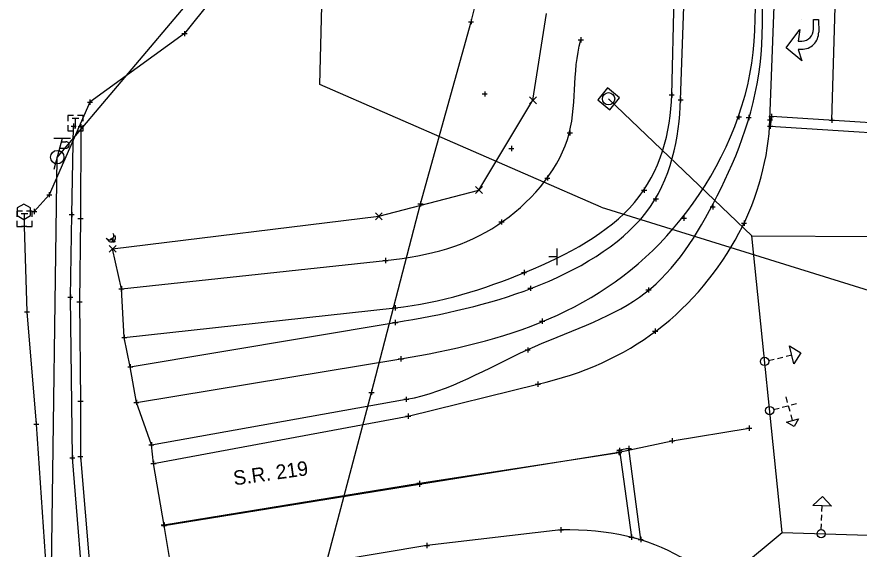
# Model space of a CAD drawing. Extents: x 1391912 to 1392597, y 304167 to 305226.
# Drawn here: x 1392159.5 to 1392322.5, y 304441.7 to 304544.7 of the extents above; entities that cross this region are included whole.
import ezdxf

# ---------------------------------------------------------------- set-up
doc = ezdxf.new("R2010")
doc.units = 0
for name, color, linetype in [('_CIVIL_CONSTRUCTION', 7, 'Continuous'), ('DV_X_Property_Line', 7, 'Continuous'), ('DV_X_Section_VMS_Line', 7, 'Continuous'), ('PM_X_Channelizing_Line', 7, 'Continuous'), ('PM_X_CL_Pass_Proh_Lt', 7, 'Continuous'), ('PM_X_Edge_Line', 7, 'Continuous'), ('PM_X_Stop_Line', 7, 'Continuous'), ('PV_X_COP', 7, 'Continuous'), ('PV_X_EOP', 7, 'Continuous'), ('PV_X_Shoulder_Aggregate', 7, 'Continuous'), ('RW_X_CL_100_Bearings', 7, 'Continuous'), ('RW_X_CL_100_Distances', 7, 'Continuous'), ('RW_X_Esmt_SH', 7, 'Continuous'), ('SC_Scratch6', 7, 'Continuous'), ('SG_X_Heads', 7, 'Continuous'), ('SG_X_Messenger_Wire', 7, 'Continuous'), ('SV_X_Break_Lines', 7, 'Continuous'), ('SV_X_Terrain_Boundary', 7, 'Continuous'), ('SV_X_Text', 7, 'Continuous'), ('SV_X_Toe_of_Slope', 7, 'Continuous'), ('SV_X_Top_of_Bank', 7, 'Continuous'), ('UT_X_FO', 7, 'Continuous'), ('UT_X_Gas', 7, 'Continuous'), ('UT_X_Overhead_Combined', 7, 'Continuous'), ('UT_X_Sanitary_Pressure_Line', 7, 'Continuous'), ('UT_X_Telecom_Cells', 7, 'Continuous')]:
    doc.layers.add(name, color=color, linetype=linetype)

msp = doc.modelspace()

# ---------------------------------------------------------------- linework, layer by layer
at = {"layer": '_CIVIL_CONSTRUCTION'}
for p, q in [((1392264, 304499.86), (1392264, 304496.66)), ((1392264, 304498.26), (1392262.4, 304498.26))]:
    msp.add_line(p, q, dxfattribs=at)
at = {"layer": 'DV_X_Property_Line'}
for p, q in [((1392311.31, 304544.17), (1392311.31, 304544.17)), ((1392313.64, 304544.19), (1392314.64, 304544.2)), ((1392313.66, 304542.33), (1392313.64, 304544.19)), ((1392314.64, 304544.2), (1392314.66, 304541.73)), ((1392308.36, 304538.71), (1392310.99, 304542.25)), ((1392310.99, 304542.25), (1392310.68, 304540.01)), ((1392310.68, 304540.01), (1392311.38, 304540.01)), ((1392311.38, 304536.17), (1392308.36, 304538.71)), ((1392311.36, 304538.41), (1392310.69, 304538.41)), ((1392310.69, 304538.41), (1392311.38, 304536.17)), ((1392311.38, 304536.17), (1392311.38, 304536.17))]:
    msp.add_line(p, q, dxfattribs=at)
for centre, radius, start in [((1392311.38, 304541.7), 3.28, 269.6131), ((1392311.36, 304542.31), 2.3, 270.5216)]:
    msp.add_arc(centre, radius, start, 0.5216, dxfattribs=at)
at = {"layer": 'DV_X_Section_VMS_Line'}
for p, q in [((1392258.7, 304527.88), (1392260.03, 304529.22)), ((1392258.7, 304529.22), (1392260.03, 304527.88)), ((1392248.24, 304510.5), (1392249.57, 304511.84)), ((1392248.24, 304511.84), (1392249.57, 304510.5)), ((1392228.85, 304505.43), (1392230.18, 304506.76)), ((1392228.85, 304506.76), (1392230.18, 304505.43)), ((1392177.33, 304499.13), (1392178.66, 304500.47)), ((1392177.33, 304500.47), (1392178.66, 304499.13))]:
    msp.add_line(p, q, dxfattribs=at)
at = {"layer": 'PM_X_Channelizing_Line'}
msp.add_lwpolyline([(1392317.22, 304524.68), (1392318.62, 304572.95), (1392319.87, 304618.22)], dxfattribs=at)
at = {"layer": 'PM_X_CL_Pass_Proh_Lt'}
msp.add_lwpolyline([(1392187.91, 304446.39), (1392237.38, 304454.42), (1392276.03, 304460.35)], dxfattribs=at)
at = {"layer": 'PM_X_Edge_Line'}
for p, q in [((1392305.23, 304524.78), (1392307, 304573.68)), ((1392235.19, 304467.42), (1392260.31, 304473.6)), ((1392185.92, 304458.25), (1392235.19, 304467.42)), ((1392264.78, 304445.4), (1392238.83, 304442.38)), ((1392238.83, 304442.38), (1392189.99, 304434.24))]:
    msp.add_line(p, q, dxfattribs=at)
for points in [[(1392260.31, 304473.6), (1392268.98, 304475.58), (1392284.55, 304482.46), (1392300.93, 304502.32), (1392304.96, 304517.51), (1392305.23, 304524.78)], [(1392310.98, 304404.01), (1392310.09, 304411.72), (1392305.75, 304424.92), (1392288.84, 304442.14), (1392274.13, 304445.52), (1392264.78, 304445.4)]]:
    msp.add_open_spline(points, degree=3, dxfattribs=at)
at = {"layer": 'PM_X_Stop_Line'}
for points in [[(1392305.5, 304525.42), (1392305.28, 304523.52), (1392341.75, 304521.19), (1392341.84, 304523.06)], [(1392278.4, 304444), (1392280.21, 304443.54), (1392277.9, 304461.18), (1392276.09, 304460.8)]]:
    msp.add_lwpolyline(points, close=True, dxfattribs=at)
at = {"layer": 'PV_X_COP'}
msp.add_lwpolyline([(1392187.94, 304446.23), (1392237.37, 304454.26), (1392275.96, 304460.46), (1392286.28, 304462.65), (1392301.21, 304465.09)], dxfattribs=at)
at = {"layer": 'PV_X_EOP'}
msp.add_line((1392185.5, 304461.86), (1392234.84, 304470.67), dxfattribs=at)
msp.add_open_spline([(1392234.84, 304470.67), (1392243.18, 304472.16), (1392258, 304481.34), (1392281.79, 304488.52), (1392294.5, 304507.17), (1392305.92, 304534.51), (1392303.1, 304556.6), (1392303.68, 304573.91)], degree=3, dxfattribs=at)
at = {"layer": 'PV_X_Shoulder_Aggregate'}
msp.add_line((1392182.59, 304470.07), (1392233.78, 304478.51), dxfattribs=at)
msp.add_open_spline([(1392233.78, 304478.51), (1392243.5, 304480.11), (1392263.28, 304484.58), (1392287.78, 304501.2), (1392305.02, 304533.31), (1392301.84, 304556.01), (1392301.83, 304573.96)], degree=3, dxfattribs=at)
at = {"layer": 'RW_X_CL_100_Bearings'}
msp.add_lwpolyline([(1392159.52, 304506.22), (1392160.81, 304505.47), (1392162.11, 304506.22), (1392162.11, 304507.72), (1392160.81, 304508.47), (1392159.52, 304507.72), (1392159.52, 304506.22)], dxfattribs=at)
at = {"layer": 'RW_X_CL_100_Distances'}
for p, q in [((1392169.84, 304521.14), (1392166.64, 304521.14)), ((1392168.24, 304521.14), (1392166.64, 304515.14)), ((1392168.08, 304520.54), (1392168.93, 304520.54)), ((1392167.74, 304519.26), (1392168.93, 304519.26))]:
    msp.add_line(p, q, dxfattribs=at)
for centre, radius in [((1392167.28, 304517.54), 1.3), ((1392177.87, 304501.68), 0.2), ((1392178.2, 304501.26), 0.2)]:
    msp.add_circle(centre, radius, dxfattribs=at)
for centre, radius, start, end in [((1392168.95, 304519.9), 0.638, 268.8767, 91.1233), ((1392177.42, 304502.34), 0.8, 214.6385, 34.6385), ((1392177.75, 304501.92), 0.8, 214.451, 34.451)]:
    msp.add_arc(centre, radius, start, end, dxfattribs=at)
at = {"layer": 'RW_X_Esmt_SH'}
for p, q in [((1392246.86, 304543.76), (1392247.86, 304543.76)), ((1392247.36, 304544.26), (1392247.36, 304543.26)), ((1392247.36, 304543.76), (1392247.36, 304543.76)), ((1392191.89, 304541.96), (1392191.89, 304540.96)), ((1392191.39, 304541.46), (1392192.39, 304541.46)), ((1392191.89, 304541.46), (1392191.89, 304541.46)), ((1392268.13, 304540.24), (1392269.13, 304540.24)), ((1392268.63, 304540.74), (1392268.63, 304539.74)), ((1392268.63, 304540.24), (1392268.63, 304540.24)), ((1392250.02, 304530.28), (1392250.02, 304529.28)), ((1392173.6, 304528.69), (1392173.6, 304527.69)), ((1392249.52, 304529.78), (1392250.52, 304529.78)), ((1392250.02, 304529.78), (1392250.02, 304529.78)), ((1392285.71, 304529.59), (1392286.71, 304529.59)), ((1392286.21, 304530.09), (1392286.21, 304529.09)), ((1392286.21, 304529.59), (1392286.21, 304529.59)), ((1392287.44, 304528.66), (1392288.44, 304528.66)), ((1392287.94, 304529.16), (1392287.94, 304528.16)), ((1392287.94, 304528.66), (1392287.94, 304528.66)), ((1392173.1, 304528.19), (1392174.1, 304528.19)), ((1392173.6, 304528.19), (1392173.6, 304528.19)), ((1392298.72, 304525.35), (1392299.72, 304525.35)), ((1392299.22, 304525.85), (1392299.22, 304524.85)), ((1392299.22, 304525.35), (1392299.22, 304525.35)), ((1392301.11, 304525.71), (1392301.11, 304524.71)), ((1392305, 304525.42), (1392306, 304525.42)), ((1392305.23, 304525.28), (1392305.23, 304524.28)), ((1392305.5, 304525.92), (1392305.5, 304524.92)), ((1392305.5, 304525.42), (1392305.5, 304525.42)), ((1392170.44, 304524.04), (1392170.44, 304523.04)), ((1392171.84, 304523.96), (1392171.84, 304522.96)), ((1392300.61, 304525.21), (1392301.61, 304525.21)), ((1392301.11, 304525.21), (1392301.11, 304525.21)), ((1392304.73, 304524.78), (1392305.73, 304524.78)), ((1392305.23, 304524.78), (1392305.23, 304524.78)), ((1392305.28, 304524.02), (1392305.28, 304523.02)), ((1392316.72, 304524.68), (1392317.72, 304524.68)), ((1392317.22, 304525.18), (1392317.22, 304524.18)), ((1392317.22, 304524.68), (1392317.22, 304524.68)), ((1392169.94, 304523.54), (1392170.94, 304523.54)), ((1392170.44, 304523.54), (1392170.44, 304523.54)), ((1392171.34, 304523.46), (1392172.34, 304523.46)), ((1392171.84, 304523.46), (1392171.84, 304523.46)), ((1392265.99, 304522.22), (1392266.99, 304522.22)), ((1392266.49, 304522.72), (1392266.49, 304521.72)), ((1392266.49, 304522.22), (1392266.49, 304522.22)), ((1392304.78, 304523.52), (1392305.78, 304523.52)), ((1392305.28, 304523.52), (1392305.28, 304523.52)), ((1392254.68, 304519.21), (1392255.68, 304519.21)), ((1392255.18, 304519.71), (1392255.18, 304518.71)), ((1392255.18, 304519.21), (1392255.18, 304519.21)), ((1392262.14, 304514), (1392262.14, 304513)), ((1392261.64, 304513.5), (1392262.64, 304513.5)), ((1392262.14, 304513.5), (1392262.14, 304513.5)), ((1392165.73, 304510.78), (1392165.73, 304509.78)), ((1392280.39, 304511.14), (1392281.39, 304511.14)), ((1392280.89, 304511.64), (1392280.89, 304510.64)), ((1392280.89, 304511.14), (1392280.89, 304511.14)), ((1392165.23, 304510.28), (1392166.23, 304510.28)), ((1392165.73, 304510.28), (1392165.73, 304510.28)), ((1392237.57, 304508.98), (1392237.57, 304507.98)), ((1392282.62, 304509.45), (1392283.62, 304509.45)), ((1392283.12, 304509.95), (1392283.12, 304508.95)), ((1392283.12, 304509.45), (1392283.12, 304509.45)), ((1392162.82, 304507.53), (1392162.82, 304506.53)), ((1392237.07, 304508.48), (1392238.07, 304508.48)), ((1392237.57, 304508.48), (1392237.57, 304508.48)), ((1392293.64, 304507.92), (1392294.64, 304507.92)), ((1392294.14, 304508.42), (1392294.14, 304507.42)), ((1392294.14, 304507.92), (1392294.14, 304507.92)), ((1392162.32, 304507.03), (1392163.32, 304507.03)), ((1392162.82, 304507.03), (1392162.82, 304507.03)), ((1392169.57, 304506.42), (1392170.57, 304506.42)), ((1392170.07, 304506.92), (1392170.07, 304505.92)), ((1392170.07, 304506.42), (1392170.07, 304506.42)), ((1392171.29, 304505.68), (1392172.29, 304505.68)), ((1392171.79, 304506.18), (1392171.79, 304505.18)), ((1392171.79, 304505.68), (1392171.79, 304505.68)), ((1392288.06, 304505.71), (1392289.06, 304505.71)), ((1392288.56, 304506.21), (1392288.56, 304505.21)), ((1392288.56, 304505.71), (1392288.56, 304505.71)), ((1392160.38, 304504.2), (1392161.38, 304504.2)), ((1392160.88, 304504.7), (1392160.88, 304503.7)), ((1392160.88, 304504.2), (1392160.88, 304504.2)), ((1392252.76, 304505), (1392253.76, 304505)), ((1392253.26, 304505.5), (1392253.26, 304504.5)), ((1392253.26, 304505), (1392253.26, 304505)), ((1392299.71, 304504.77), (1392300.71, 304504.77)), ((1392300.21, 304505.27), (1392300.21, 304504.27)), ((1392300.21, 304504.77), (1392300.21, 304504.77)), ((1392230.31, 304497.55), (1392231.31, 304497.55)), ((1392230.81, 304498.05), (1392230.81, 304497.05)), ((1392230.81, 304497.55), (1392230.81, 304497.55)), ((1392257.13, 304495.22), (1392258.13, 304495.22)), ((1392257.63, 304495.72), (1392257.63, 304494.72)), ((1392257.63, 304495.22), (1392257.63, 304495.22)), ((1392258.86, 304492.66), (1392258.86, 304491.66)), ((1392179.18, 304492.06), (1392180.18, 304492.06)), ((1392179.68, 304492.56), (1392179.68, 304491.56)), ((1392179.68, 304492.06), (1392179.68, 304492.06)), ((1392258.36, 304492.16), (1392259.36, 304492.16)), ((1392258.86, 304492.16), (1392258.86, 304492.16)), ((1392281.22, 304491.84), (1392282.22, 304491.84)), ((1392281.72, 304492.34), (1392281.72, 304491.34)), ((1392281.72, 304491.84), (1392281.72, 304491.84)), ((1392169.31, 304490.44), (1392170.31, 304490.44)), ((1392169.81, 304490.94), (1392169.81, 304489.94)), ((1392169.81, 304490.44), (1392169.81, 304490.44)), ((1392171.09, 304489.53), (1392172.09, 304489.53)), ((1392171.59, 304490.03), (1392171.59, 304489.03)), ((1392171.59, 304489.53), (1392171.59, 304489.53)), ((1392161.41, 304488.13), (1392161.41, 304487.13)), ((1392232.16, 304488.37), (1392233.16, 304488.37)), ((1392232.66, 304488.87), (1392232.66, 304487.87)), ((1392232.66, 304488.37), (1392232.66, 304488.37)), ((1392160.91, 304487.63), (1392161.91, 304487.63)), ((1392161.41, 304487.63), (1392161.41, 304487.63)), ((1392261.14, 304486.29), (1392261.14, 304485.29)), ((1392232.17, 304485.54), (1392233.17, 304485.54)), ((1392232.67, 304486.04), (1392232.67, 304485.04)), ((1392232.67, 304485.54), (1392232.67, 304485.54)), ((1392260.64, 304485.79), (1392261.64, 304485.79)), ((1392261.14, 304485.79), (1392261.14, 304485.79)), ((1392180.25, 304483.13), (1392180.25, 304482.13)), ((1392282.52, 304483.85), (1392283.52, 304483.85)), ((1392283.02, 304484.35), (1392283.02, 304483.35)), ((1392283.02, 304483.85), (1392283.02, 304483.85)), ((1392179.75, 304482.63), (1392180.75, 304482.63)), ((1392180.25, 304482.63), (1392180.25, 304482.63)), ((1392257.83, 304480.23), (1392258.83, 304480.23)), ((1392258.33, 304480.73), (1392258.33, 304479.73)), ((1392258.33, 304480.23), (1392258.33, 304480.23)), ((1392233.28, 304478.51), (1392234.28, 304478.51)), ((1392233.78, 304479.01), (1392233.78, 304478.01)), ((1392233.78, 304478.51), (1392233.78, 304478.51)), ((1392180.92, 304476.96), (1392181.92, 304476.96)), ((1392181.42, 304477.46), (1392181.42, 304476.46)), ((1392181.42, 304476.96), (1392181.42, 304476.96)), ((1392259.81, 304473.6), (1392260.81, 304473.6)), ((1392260.31, 304474.1), (1392260.31, 304473.1)), ((1392260.31, 304473.6), (1392260.31, 304473.6)), ((1392227.6, 304472.01), (1392228.6, 304472.01)), ((1392228.1, 304472.51), (1392228.1, 304471.51)), ((1392228.1, 304472.01), (1392228.1, 304472.01)), ((1392171.26, 304470.32), (1392172.26, 304470.32)), ((1392171.76, 304470.82), (1392171.76, 304469.82)), ((1392171.76, 304470.32), (1392171.76, 304470.32)), ((1392182.09, 304470.07), (1392183.09, 304470.07)), ((1392182.59, 304470.57), (1392182.59, 304469.57)), ((1392182.59, 304470.07), (1392182.59, 304470.07)), ((1392234.34, 304470.67), (1392235.34, 304470.67)), ((1392234.84, 304471.17), (1392234.84, 304470.17)), ((1392234.84, 304470.67), (1392234.84, 304470.67)), ((1392234.69, 304467.42), (1392235.69, 304467.42)), ((1392235.19, 304467.92), (1392235.19, 304466.92)), ((1392235.19, 304467.42), (1392235.19, 304467.42)), ((1392162.72, 304465.88), (1392163.72, 304465.88)), ((1392163.22, 304466.38), (1392163.22, 304465.38)), ((1392163.22, 304465.88), (1392163.22, 304465.88)), ((1392300.71, 304465.09), (1392301.71, 304465.09)), ((1392301.21, 304465.59), (1392301.21, 304464.59)), ((1392301.21, 304465.09), (1392301.21, 304465.09)), ((1392185, 304461.86), (1392186, 304461.86)), ((1392185.5, 304462.36), (1392185.5, 304461.36)), ((1392185.5, 304461.86), (1392185.5, 304461.86)), ((1392277.9, 304461.68), (1392277.9, 304460.68)), ((1392285.78, 304462.65), (1392286.78, 304462.65)), ((1392286.28, 304463.15), (1392286.28, 304462.15)), ((1392286.28, 304462.65), (1392286.28, 304462.65)), ((1392171.75, 304460.11), (1392171.75, 304459.11)), ((1392275.46, 304460.46), (1392276.46, 304460.46)), ((1392275.53, 304460.35), (1392276.53, 304460.35)), ((1392275.59, 304460.8), (1392276.59, 304460.8)), ((1392275.96, 304460.96), (1392275.96, 304459.96)), ((1392275.96, 304460.46), (1392275.96, 304460.46)), ((1392276.03, 304460.85), (1392276.03, 304459.85)), ((1392276.03, 304460.35), (1392276.03, 304460.35)), ((1392276.09, 304461.3), (1392276.09, 304460.3)), ((1392276.09, 304460.8), (1392276.09, 304460.8)), ((1392277.4, 304461.18), (1392278.4, 304461.18)), ((1392277.9, 304461.18), (1392277.9, 304461.18)), ((1392169.7, 304459.35), (1392170.7, 304459.35)), ((1392170.2, 304459.85), (1392170.2, 304458.85)), ((1392170.2, 304459.35), (1392170.2, 304459.35)), ((1392171.25, 304459.61), (1392172.25, 304459.61)), ((1392171.75, 304459.61), (1392171.75, 304459.61)), ((1392185.92, 304458.75), (1392185.92, 304457.75)), ((1392185.42, 304458.25), (1392186.42, 304458.25)), ((1392185.92, 304458.25), (1392185.92, 304458.25)), ((1392236.87, 304454.26), (1392237.87, 304454.26)), ((1392236.88, 304454.42), (1392237.88, 304454.42)), ((1392237.37, 304454.76), (1392237.37, 304453.76)), ((1392237.37, 304454.26), (1392237.37, 304454.26)), ((1392237.38, 304454.92), (1392237.38, 304453.92)), ((1392237.38, 304454.42), (1392237.38, 304454.42)), ((1392187.41, 304446.39), (1392188.41, 304446.39)), ((1392187.44, 304446.23), (1392188.44, 304446.23)), ((1392187.91, 304446.89), (1392187.91, 304445.89)), ((1392187.91, 304446.39), (1392187.91, 304446.39)), ((1392187.94, 304446.73), (1392187.94, 304445.73)), ((1392187.94, 304446.23), (1392187.94, 304446.23)), ((1392264.28, 304445.4), (1392265.28, 304445.4)), ((1392264.78, 304445.9), (1392264.78, 304444.9)), ((1392264.78, 304445.4), (1392264.78, 304445.4)), ((1392277.9, 304444), (1392278.9, 304444)), ((1392278.4, 304444.5), (1392278.4, 304443.5)), ((1392278.4, 304444), (1392278.4, 304444)), ((1392280.21, 304444.04), (1392280.21, 304443.04)), ((1392238.33, 304442.38), (1392239.33, 304442.38)), ((1392238.83, 304442.88), (1392238.83, 304441.88)), ((1392238.83, 304442.38), (1392238.83, 304442.38)), ((1392279.71, 304443.54), (1392280.71, 304443.54)), ((1392280.21, 304443.54), (1392280.21, 304443.54))]:
    msp.add_line(p, q, dxfattribs=at)
at = {"layer": 'SC_Scratch6'}
msp.add_lwpolyline([(1392271.88, 304528.62), (1392274.2, 304526.72), (1392276.1, 304529.05), (1392273.78, 304530.95)], close=True, dxfattribs=at)
msp.add_circle((1392273.99, 304528.84), 1.2, dxfattribs=at)
at = {"layer": 'SG_X_Heads'}
for p, q in [((1392304.96, 304478.19), (1392306.03, 304478.44)), ((1392306.66, 304478.6), (1392307.73, 304478.85)), ((1392308.36, 304479), (1392309.43, 304479.26)), ((1392308.65, 304470.06), (1392308.37, 304471.12)), ((1392309.31, 304469.6), (1392310.37, 304469.89)), ((1392305.93, 304468.69), (1392306.99, 304468.98)), ((1392307.62, 304469.15), (1392308.68, 304469.43)), ((1392309.12, 304468.32), (1392308.83, 304469.39)), ((1392309.58, 304466.59), (1392309.3, 304467.65)), ((1392315.28, 304448.95), (1392315.31, 304450.05)), ((1392315.22, 304447.2), (1392315.26, 304448.3)), ((1392315.16, 304445.45), (1392315.2, 304446.55))]:
    msp.add_line(p, q, dxfattribs=at)
for points in [[(1392309.01, 304481.01), (1392311.18, 304479.68), (1392309.85, 304477.51)], [(1392310.75, 304466.9), (1392309.9, 304465.43), (1392308.43, 304466.27)], [(1392313.51, 304450.11), (1392315.37, 304451.85), (1392317.11, 304449.99)]]:
    msp.add_lwpolyline(points, close=True, dxfattribs=at)
for centre in [(1392304.18, 304478), (1392305.16, 304468.49), (1392315.14, 304444.65)]:
    msp.add_circle(centre, 0.8, dxfattribs=at)
at = {"layer": 'SG_X_Messenger_Wire'}
for p, q in [((1392301.69, 304502.33), (1392273.99, 304528.84)), ((1392307.57, 304444.87), (1392301.69, 304502.33)), ((1392301.69, 304502.33), (1392361.08, 304501.95)), ((1392273.77, 304416.86), (1392307.57, 304444.87)), ((1392307.57, 304444.87), (1392367.29, 304443.16))]:
    msp.add_line(p, q, dxfattribs=at)
at = {"layer": 'SV_X_Break_Lines'}
for p, q in [((1392286.21, 304529.59), (1392287.32, 304574.56)), ((1392180.25, 304482.63), (1392232.66, 304488.37))]:
    msp.add_line(p, q, dxfattribs=at)
msp.add_open_spline([(1392232.66, 304488.37), (1392241.56, 304489.35), (1392258.06, 304494.49), (1392282.01, 304507.03), (1392286.04, 304522.41), (1392286.21, 304529.59)], degree=3, dxfattribs=at)
at = {"layer": 'SV_X_Terrain_Boundary'}
msp.add_lwpolyline([(1392189.99, 304434.24), (1392187.94, 304446.23), (1392185.92, 304458.25), (1392185.5, 304461.86), (1392182.59, 304470.07), (1392181.42, 304476.96), (1392180.25, 304482.63), (1392179.68, 304492.06), (1392177.99, 304499.8), (1392229.51, 304506.1), (1392248.9, 304511.17), (1392259.36, 304528.55), (1392261.98, 304545.38)], dxfattribs=at)
at = {"layer": 'SV_X_Toe_of_Slope'}
for p, q in [((1392287.94, 304528.66), (1392289.48, 304574.36)), ((1392181.42, 304476.96), (1392232.67, 304485.54))]:
    msp.add_line(p, q, dxfattribs=at)
msp.add_open_spline([(1392232.67, 304485.54), (1392241.96, 304487.1), (1392259.45, 304490.76), (1392284.6, 304505.12), (1392287.69, 304521.23), (1392287.94, 304528.66)], degree=3, dxfattribs=at)
at = {"layer": 'SV_X_Top_of_Bank'}
msp.add_line((1392179.68, 304492.06), (1392230.81, 304497.55), dxfattribs=at)
msp.add_open_spline([(1392230.81, 304497.55), (1392239.66, 304498.49), (1392253.25, 304502.3), (1392269.33, 304520.69), (1392266.8, 304533.91), (1392268.63, 304540.24)], degree=3, dxfattribs=at)
at = {"layer": 'UT_X_FO'}
for points in [[(1392265.55, 304636.24), (1392244.15, 304606.72), (1392191.89, 304541.46), (1392173.6, 304528.19), (1392165.73, 304510.28), (1392162.82, 304507.03)], [(1392177.42, 304398.84), (1392176.52, 304401.4), (1392172.88, 304426.71), (1392170.2, 304459.35), (1392169.81, 304490.44), (1392170.07, 304506.42), (1392170.44, 304523.54)], [(1392171.84, 304523.46), (1392171.79, 304505.68), (1392171.59, 304489.53), (1392171.76, 304470.32), (1392171.75, 304459.61), (1392174.56, 304426.47), (1392178.18, 304398.79)], [(1392160.88, 304504.2), (1392161.41, 304487.63), (1392163.22, 304465.88), (1392165.35, 304434.6), (1392165.62, 304411.18), (1392177.02, 304398.53)]]:
    msp.add_lwpolyline(points, dxfattribs=at)
at = {"layer": 'UT_X_Gas'}
msp.add_lwpolyline([(1392208.68, 304383.14), (1392209.86, 304403.85), (1392217.44, 304431.72), (1392228.1, 304472.01), (1392237.57, 304508.48), (1392247.36, 304543.76), (1392255.82, 304577.61)], dxfattribs=at)
at = {"layer": 'UT_X_Overhead_Combined'}
for p, q in [((1392167.24, 304517.47), (1392271.74, 304640.95)), ((1392165.2, 304370.85), (1392167.24, 304517.47))]:
    msp.add_line(p, q, dxfattribs=at)
at = {"layer": 'UT_X_Sanitary_Pressure_Line'}
for q in [(1392218.1, 304531.61), (1392412.78, 304464.28)]:
    msp.add_line((1392272.56, 304507.86), q, dxfattribs=at)
msp.add_lwpolyline([(1392218.1, 304531.61), (1392220.79, 304638.44)], dxfattribs=at)
at = {"layer": 'UT_X_Telecom_Cells'}
for p, q in [((1392170.17, 304525.11), (1392171.47, 304525.11)), ((1392170.82, 304523.11), (1392170.82, 304525.11)), ((1392170.82, 304524.11), (1392170.82, 304524.11)), ((1392160.3, 304506.62), (1392161.6, 304506.62)), ((1392160.95, 304504.62), (1392160.95, 304506.62)), ((1392160.95, 304505.62), (1392160.95, 304505.62))]:
    msp.add_line(p, q, dxfattribs=at)
for points in [[(1392170.42, 304525.61), (1392169.32, 304525.61), (1392169.32, 304524.51)], [(1392172.32, 304524.51), (1392172.32, 304525.61), (1392171.22, 304525.61)], [(1392169.32, 304523.71), (1392169.32, 304522.61), (1392170.42, 304522.61)], [(1392171.22, 304522.61), (1392172.32, 304522.61), (1392172.32, 304523.71)], [(1392160.55, 304507.12), (1392159.45, 304507.12), (1392159.45, 304506.02)], [(1392162.45, 304506.02), (1392162.45, 304507.12), (1392161.35, 304507.12)], [(1392159.45, 304505.22), (1392159.45, 304504.12), (1392160.55, 304504.12)], [(1392161.35, 304504.12), (1392162.45, 304504.12), (1392162.45, 304505.22)]]:
    msp.add_lwpolyline(points, dxfattribs=at)

# ---------------------------------------------------------------- texts
at = {"layer": 'SV_X_Text'}
msp.add_text('S.R. 219', height=2.8, rotation=7.9143, dxfattribs=at).set_placement((1392201.55, 304454))

doc.saveas('drawing.dxf')
